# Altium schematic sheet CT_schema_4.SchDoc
size 401 x 230 mm
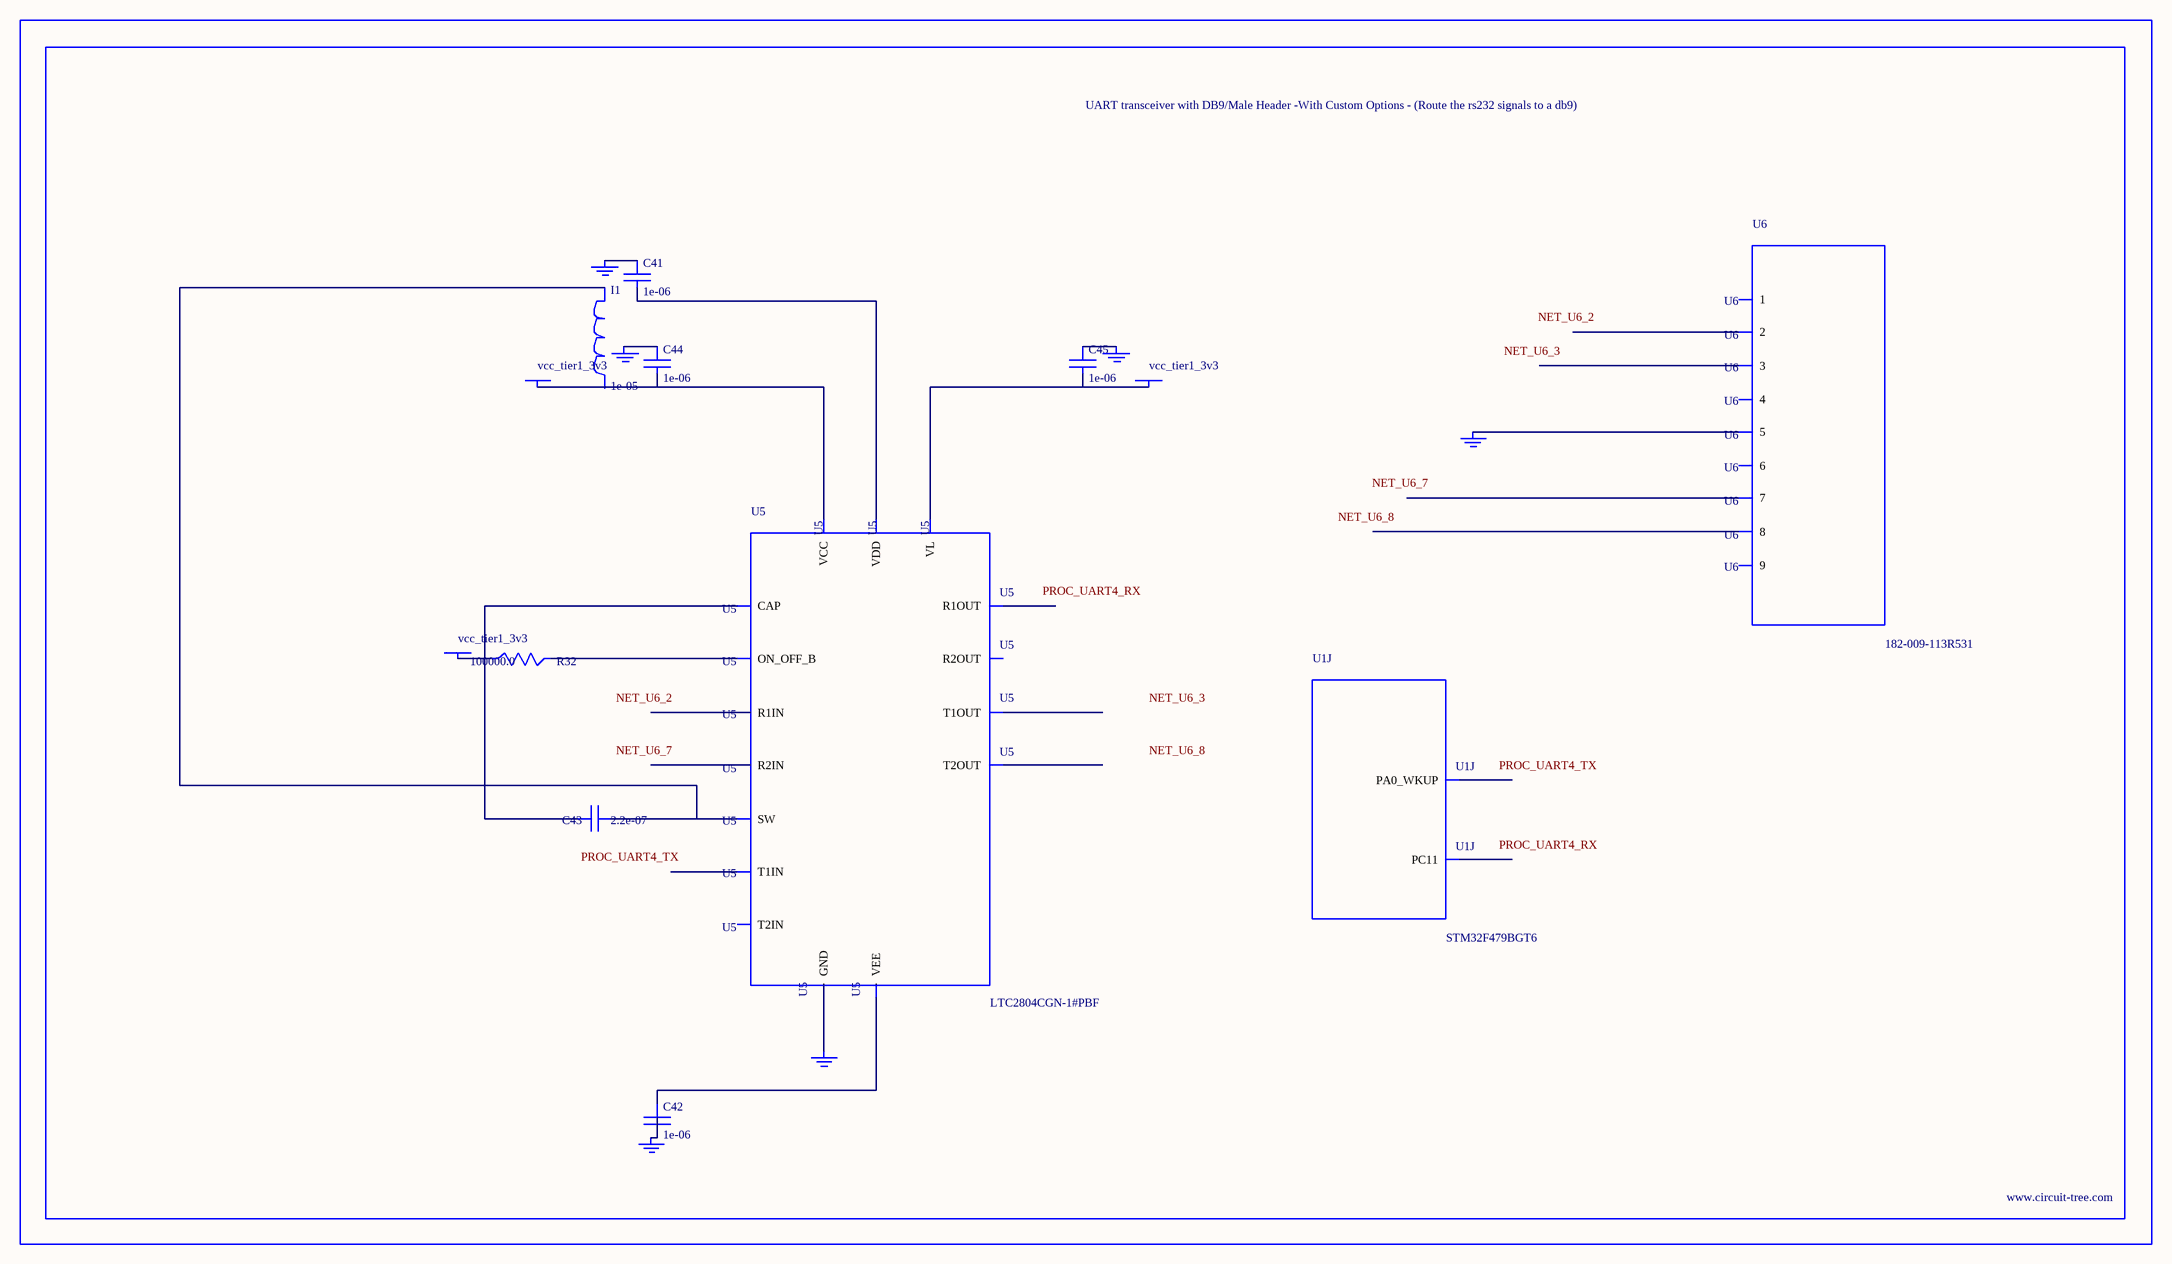
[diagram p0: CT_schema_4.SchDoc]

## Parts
BORDER3  (no value)
C41  1e-06  [C0603]
C42  1e-06  [C0603]
C43  2.2e-07  [C0603]
C44  1e-06  [C0603]
C45  1e-06  [C0603]
GND_INSTANCE_3_0  (no value)
GND_INSTANCE_3_1  (no value)
GND_INSTANCE_3_2  (no value)
GND_INSTANCE_3_3  (no value)
GND_INSTANCE_3_4  (no value)
GND_INSTANCE_3_5  (no value)
I1  1e-05  [L1210]
POWER_INSTANCE_3_0  vcc_tier1_3v3
POWER_INSTANCE_3_1  vcc_tier1_3v3
POWER_INSTANCE_3_2  vcc_tier1_3v3
R32  100000.0  [R0603]
U1  STM32F479BGT6  [LQFP208]  (part J of 16)
U5  LTC2804CGN-1#PBF  [SSOP-16]
U6  182-009-113R531  [182-009-MALE]

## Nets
NetC41_1: C41.1 GND_INSTANCE_3_1.0(GND)
NetC41_2: C41.2 U5.6(VDD)
NetC42_1: C42.1 U5.9(VEE)
NetC42_2: C42.2 GND_INSTANCE_3_2.0(GND)
NetC43_1: C43.1 I1.1 U5.7(SW)
NetC43_2: C43.2 U5.10(CAP)
NetC44_1: C44.1 GND_INSTANCE_3_0.0(GND)
NetC44_2: C44.2 POWER_INSTANCE_3_0.0(PWR) U5.5(VCC)
NetC45_1: C45.1 GND_INSTANCE_3_3.0(GND)
NetC45_2: C45.2 POWER_INSTANCE_3_2.0(PWR) U5.12(VL)
NetGND_INSTANCE_3_4_0: GND_INSTANCE_3_4.0(GND) U5.8(GND)
NetGND_INSTANCE_3_5_0: GND_INSTANCE_3_5.0(GND) U6.5
NetPOWER_INSTANCE_3_1_0: POWER_INSTANCE_3_1.0(PWR) R32.1
NetR32_2: R32.2 U5.11(ON_OFF_B)

Not connected (* = marked no-connect by the designer): I1 2; U1 43(PA0_WKUP) 162(PC11); U5 1(R1IN) 2(R2IN) 3(T1OUT) 4(T2OUT) 13(T2IN) 14(T1IN) 15(R2OUT) 16(R1OUT); U6 1 2 3 4 6 7 8 9

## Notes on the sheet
- Labels drawn without touching a wire or pin: NET_U6_2, NET_U6_3, NET_U6_7, NET_U6_8, PROC_UART4_RX, PROC_UART4_TX

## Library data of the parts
BORDER3 = BORDER_PAGE3
C41 C42 C44 C45 = C0603C105K3RACTU
C43 = C0603C224K3RAC
GND_INSTANCE_3_0-GND_INSTANCE_3_5 = GND
I1 = CBC3225T100MR
POWER_INSTANCE_3_0-POWER_INSTANCE_3_2 = PWR
R32 = RC0603JR-07100KL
